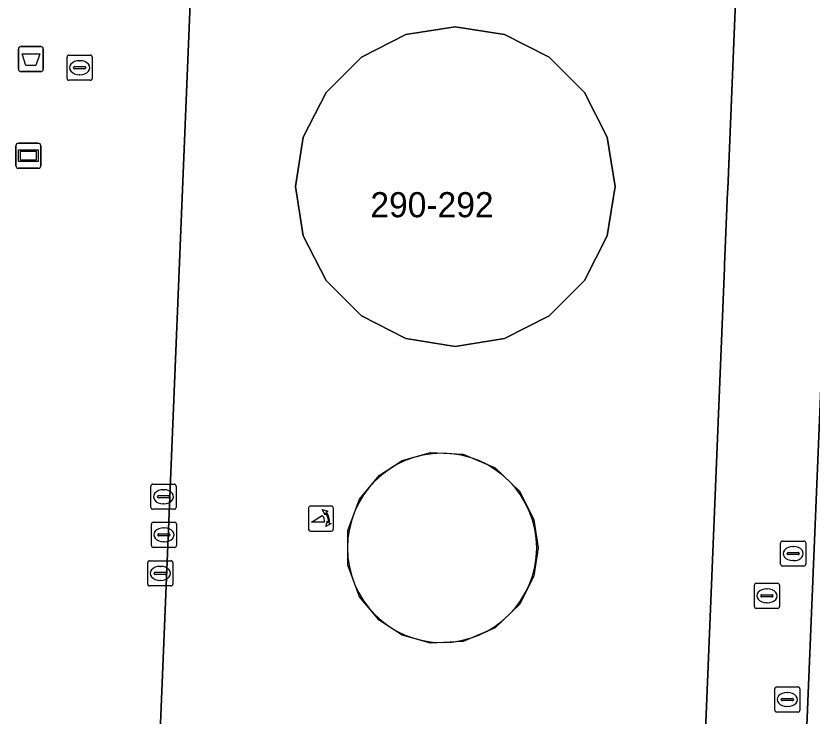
# Model space of a CAD drawing. Extents: x 160888 to 161385, y 386490 to 386908.
# Drawn here: x 161238.26 to 161269.97, y 386705.95 to 386733.83 of the extents above; entities that cross this region are included whole.
import ezdxf

# ---------------------------------------------------------------- set-up
doc = ezdxf.new("R2010")
doc.units = 0
for name, color, linetype in [('IMGEO_Afvalbak', 7, 'Continuous'), ('IMGEO_Kolk', 7, 'Continuous'), ('IMGEO_Pand', 7, 'Continuous'), ('IMGEO_Pand_nummerreeks', 7, 'Continuous'), ('IMGEO_Pand_overbouw', 7, 'Continuous'), ('IMGEO_Poller', 7, 'Continuous'), ('IMGEO_Reclamebord', 7, 'Continuous'), ('IMGEO_Rioolput', 7, 'Continuous'), ('IMGEO_Voetgangersgebied_open', 7, 'Continuous'), ('IMGEO_Voetpad_open', 7, 'Continuous')]:
    doc.layers.add(name, color=color, linetype=linetype)

msp = doc.modelspace()

# ---------------------------------------------------------------- linework, layer by layer
at = {"layer": 'IMGEO_Afvalbak'}
for p, q in [((161238.358, 386731.708), (161238.358, 386732.508)), ((161238.358, 386732.508), (161238.358, 386731.708)), ((161238.458, 386732.608), (161239.248, 386732.608)), ((161239.248, 386732.608), (161238.458, 386732.608)), ((161239.348, 386732.508), (161239.348, 386731.708)), ((161239.348, 386731.708), (161239.348, 386732.508)), ((161239.248, 386731.608), (161238.458, 386731.608)), ((161238.458, 386731.608), (161239.248, 386731.608))]:
    msp.add_line(p, q, dxfattribs=at)
msp.add_lwpolyline([(161238.501, 386732.322), (161239.205, 386732.322), (161239.056, 386731.852), (161238.65, 386731.852), (161238.501, 386732.322)], dxfattribs=at)
for centre, start, end in [((161238.458, 386732.508), 90, 180), ((161238.458, 386732.508), 90, 180), ((161239.248, 386732.508), 0, 90), ((161239.248, 386732.508), 360, 90), ((161238.458, 386731.708), 180, 270), ((161238.458, 386731.708), 180, 270), ((161239.248, 386731.708), 270, 0), ((161239.248, 386731.708), 270, 0)]:
    msp.add_arc(centre, 0.1, start, end, dxfattribs=at)
at = {"layer": 'IMGEO_Kolk'}
for p, q in [((161240.293, 386731.339), (161240.293, 386732.191)), ((161240.368, 386732.265), (161241.22, 386732.265)), ((161241.294, 386732.191), (161241.294, 386731.339)), ((161240.781, 386732.045), (161240.806, 386732.045)), ((161240.552, 386731.759), (161240.552, 386731.771)), ((161240.99, 386731.722), (161240.592, 386731.722)), ((161240.595, 386731.808), (161240.993, 386731.808)), ((161241.036, 386731.771), (161241.036, 386731.759)), ((161241.22, 386731.265), (161240.368, 386731.265)), ((161240.804, 386731.485), (161240.779, 386731.485))]:
    msp.add_line(p, q, dxfattribs=at)
for points in [[(161240.293, 386731.339), (161240.293, 386732.191)], [(161240.368, 386732.265), (161241.22, 386732.265)], [(161241.294, 386732.191), (161241.294, 386731.339)], [(161241.22, 386731.265), (161240.368, 386731.265)]]:
    msp.add_lwpolyline(points, dxfattribs=at)
for centre, radius, start, end in [((161240.37, 386732.189), 0.0765, 91.552, 178.448), ((161240.37, 386732.189), 0.0765, 91.552, 178.448), ((161241.218, 386732.189), 0.0765, 1.552, 88.448), ((161241.218, 386732.189), 0.0765, 1.552, 88.448), ((161240.592, 386731.768), 0.0403, 85.8775, 175.7526), ((161240.589, 386731.758), 0.0366, 178.938, 274.7102), ((161240.993, 386731.765), 0.043, 264.8664, 352.4533), ((161240.997, 386731.77), 0.0386, 1.7309, 96.639), ((161240.37, 386731.341), 0.0765, 181.552, 268.448), ((161240.37, 386731.341), 0.0765, 181.552, 268.448), ((161241.218, 386731.341), 0.0765, 271.552, 358.448), ((161241.218, 386731.341), 0.0765, 271.552, 358.448)]:
    msp.add_arc(centre, radius, start, end, dxfattribs=at)
for centre, major_axis, ratio, start_param, end_param in [((161240.78, 386731.765), (-0.387, 0.002), 0.722429, 4.712389, 7.853982), ((161240.805, 386731.765), (-0.39, 0.002), 0.717154, 1.570796, 4.712389)]:
    msp.add_ellipse(centre, major_axis=major_axis, ratio=ratio, start_param=start_param, end_param=end_param, dxfattribs=at)
at = {"layer": 'IMGEO_Pand'}
msp.add_lwpolyline([(161257.725, 386720.977), (161259.499, 386721.882), (161260.908, 386723.29), (161261.812, 386725.064), (161262.123, 386727.031), (161261.812, 386728.998), (161260.908, 386730.772), (161259.499, 386732.18), (161257.725, 386733.084), (161255.758, 386733.396), (161253.791, 386733.084), (161252.017, 386732.18), (161250.609, 386730.772), (161249.705, 386728.998), (161249.393, 386727.031), (161249.705, 386725.064), (161250.609, 386723.29), (161252.017, 386721.882), (161253.791, 386720.977), (161255.758, 386720.666)], close=True, dxfattribs=at)
at = {"layer": 'IMGEO_Pand_overbouw'}
for points in [[(161267.088, 386738.621), (161245.413, 386739.487), (161243.237, 386686.658), (161264.93, 386685.782)], [(161257.725, 386720.977), (161255.758, 386720.666), (161253.791, 386720.977), (161252.017, 386721.882), (161250.609, 386723.29), (161249.705, 386725.064), (161249.393, 386727.031), (161249.705, 386728.998), (161250.609, 386730.772), (161252.017, 386732.18), (161253.791, 386733.084), (161255.758, 386733.396), (161257.725, 386733.084), (161259.499, 386732.18), (161260.908, 386730.772), (161261.812, 386728.998), (161262.123, 386727.031), (161261.812, 386725.064), (161260.908, 386723.29), (161259.499, 386721.882)], [(161259.055, 386712.644), (161258.89, 386711.533), (161258.325, 386710.398), (161257.341, 386709.456), (161256.074, 386708.915), (161254.769, 386708.85), (161253.639, 386709.169), (161252.725, 386709.759), (161251.942, 386710.698), (161251.473, 386711.952), (161251.473, 386713.335), (161251.942, 386714.589), (161252.725, 386715.529), (161253.639, 386716.118), (161254.769, 386716.438), (161256.074, 386716.372), (161257.341, 386715.832), (161258.325, 386714.889), (161258.89, 386713.754)]]:
    msp.add_lwpolyline(points, close=True, dxfattribs=at)
at = {"layer": 'IMGEO_Poller'}
for p, q in [((161249.91, 386714.213), (161249.91, 386713.406)), ((161249.91, 386714.213), (161249.91, 386713.406)), ((161250.812, 386714.308), (161250.004, 386714.308)), ((161250.812, 386714.308), (161250.004, 386714.308)), ((161250.906, 386713.406), (161250.906, 386714.213)), ((161250.906, 386713.406), (161250.906, 386714.213)), ((161250.004, 386713.311), (161250.812, 386713.311)), ((161250.004, 386713.311), (161250.812, 386713.311))]:
    msp.add_line(p, q, dxfattribs=at)
for points in [[(161250.589, 386714.037), (161250.577, 386713.964), (161250.452, 386714.169)], [(161250.452, 386714.169), (161250.683, 386714.103), (161250.612, 386714.071)], [(161250.545, 386713.664), (161250.032, 386713.664), (161250.462, 386713.939)], [(161250.605, 386713.492), (161250.671, 386713.723), (161250.701, 386713.655)], [(161250.737, 386713.628), (161250.809, 386713.617), (161250.605, 386713.492)]]:
    msp.add_lwpolyline(points, dxfattribs=at)
for centre, radius, start, end in [((161250.004, 386714.213), 0.0946, 90, 180), ((161250.004, 386714.213), 0.0946, 90, 180), ((161250.812, 386714.213), 0.0946, 0, 90), ((161250.812, 386714.213), 0.0946, 0, 90), ((161250.217, 386713.714), 0.332, 351.3247, 42.4854), ((161250.231, 386713.724), 0.476, 351.7527, 41.1691), ((161250.231, 386713.724), 0.516, 349.3569, 42.2912), ((161250.004, 386713.406), 0.0946, 180, 270), ((161250.004, 386713.406), 0.0946, 180, 270), ((161250.812, 386713.406), 0.0946, 270, 0), ((161250.812, 386713.406), 0.0946, 270, 0)]:
    msp.add_arc(centre, radius, start, end, dxfattribs=at)
at = {"layer": 'IMGEO_Reclamebord'}
for p, q in [((161238.357, 386728.759), (161239.147, 386728.759)), ((161239.147, 386728.759), (161238.357, 386728.759)), ((161238.257, 386727.859), (161238.257, 386728.659)), ((161238.257, 386728.659), (161238.257, 386727.859)), ((161239.247, 386728.659), (161239.247, 386727.859)), ((161239.247, 386727.859), (161239.247, 386728.659)), ((161239.147, 386727.759), (161238.357, 386727.759)), ((161238.357, 386727.759), (161239.147, 386727.759))]:
    msp.add_line(p, q, dxfattribs=at)
for points in [[(161238.358, 386728.491), (161239.146, 386728.491), (161239.146, 386728.027), (161238.358, 386728.027), (161238.358, 386728.491)], [(161238.423, 386728.426), (161238.423, 386728.092), (161239.081, 386728.092), (161239.081, 386728.426), (161238.423, 386728.426)]]:
    msp.add_lwpolyline(points, dxfattribs=at)
for centre, start, end in [((161238.357, 386728.659), 90, 180), ((161238.357, 386728.659), 90, 180), ((161239.147, 386728.659), 0, 90), ((161239.147, 386728.659), 360, 90), ((161238.357, 386727.859), 180, 270), ((161238.357, 386727.859), 180, 270), ((161239.147, 386727.859), 270, 0), ((161239.147, 386727.859), 270, 0)]:
    msp.add_arc(centre, 0.1, start, end, dxfattribs=at)
at = {"layer": 'IMGEO_Rioolput'}
for p, q in [((161243.637, 386714.254), (161243.637, 386715.106)), ((161243.712, 386715.18), (161244.564, 386715.18)), ((161244.638, 386715.106), (161244.638, 386714.254)), ((161244.125, 386714.96), (161244.15, 386714.96)), ((161243.896, 386714.674), (161243.896, 386714.686)), ((161244.334, 386714.637), (161243.936, 386714.637)), ((161243.939, 386714.723), (161244.337, 386714.723)), ((161244.38, 386714.686), (161244.38, 386714.674)), ((161244.564, 386714.18), (161243.712, 386714.18)), ((161244.148, 386714.4), (161244.123, 386714.4)), ((161243.652, 386712.737), (161243.652, 386713.589)), ((161243.727, 386713.663), (161244.579, 386713.663)), ((161244.653, 386713.589), (161244.653, 386712.737)), ((161243.911, 386713.157), (161243.911, 386713.169)), ((161243.954, 386713.206), (161244.352, 386713.206)), ((161244.14, 386713.443), (161244.165, 386713.443)), ((161244.395, 386713.169), (161244.395, 386713.157)), ((161244.349, 386713.12), (161243.951, 386713.12)), ((161244.163, 386712.883), (161244.138, 386712.883)), ((161268.719, 386711.991), (161268.719, 386712.843)), ((161268.794, 386712.917), (161269.646, 386712.917)), ((161269.72, 386712.843), (161269.72, 386711.991)), ((161244.579, 386712.663), (161243.727, 386712.663)), ((161269.207, 386712.697), (161269.232, 386712.697)), ((161268.978, 386712.411), (161268.978, 386712.423)), ((161269.416, 386712.374), (161269.018, 386712.374)), ((161269.021, 386712.46), (161269.419, 386712.46)), ((161269.462, 386712.423), (161269.462, 386712.411)), ((161243.506, 386711.202), (161243.506, 386712.054)), ((161243.581, 386712.128), (161244.433, 386712.128)), ((161243.994, 386711.908), (161244.019, 386711.908)), ((161244.507, 386712.054), (161244.507, 386711.202)), ((161269.646, 386711.917), (161268.794, 386711.917)), ((161269.23, 386712.137), (161269.205, 386712.137)), ((161243.765, 386711.622), (161243.765, 386711.634)), ((161244.203, 386711.585), (161243.805, 386711.585)), ((161243.808, 386711.671), (161244.206, 386711.671)), ((161244.249, 386711.634), (161244.249, 386711.622)), ((161244.017, 386711.348), (161243.992, 386711.348)), ((161244.433, 386711.128), (161243.581, 386711.128)), ((161267.673, 386710.308), (161267.673, 386711.16)), ((161267.748, 386711.234), (161268.6, 386711.234)), ((161268.161, 386711.014), (161268.186, 386711.014)), ((161268.674, 386711.16), (161268.674, 386710.308)), ((161267.932, 386710.728), (161267.932, 386710.74)), ((161268.37, 386710.691), (161267.972, 386710.691)), ((161267.975, 386710.777), (161268.373, 386710.777)), ((161268.416, 386710.74), (161268.416, 386710.728)), ((161268.184, 386710.454), (161268.159, 386710.454)), ((161268.6, 386710.234), (161267.748, 386710.234)), ((161268.485, 386706.178), (161268.485, 386707.03)), ((161268.56, 386707.104), (161269.412, 386707.104)), ((161268.973, 386706.884), (161268.998, 386706.884)), ((161269.486, 386707.03), (161269.486, 386706.178)), ((161268.744, 386706.598), (161268.744, 386706.61)), ((161269.182, 386706.561), (161268.784, 386706.561)), ((161268.787, 386706.647), (161269.185, 386706.647)), ((161269.228, 386706.61), (161269.228, 386706.598)), ((161268.996, 386706.324), (161268.971, 386706.324)), ((161269.412, 386706.104), (161268.56, 386706.104))]:
    msp.add_line(p, q, dxfattribs=at)
for points in [[(161243.637, 386714.254), (161243.637, 386715.106)], [(161243.712, 386715.18), (161244.564, 386715.18)], [(161244.638, 386715.106), (161244.638, 386714.254)], [(161244.564, 386714.18), (161243.712, 386714.18)], [(161243.652, 386712.737), (161243.652, 386713.589)], [(161243.727, 386713.663), (161244.579, 386713.663)], [(161244.653, 386713.589), (161244.653, 386712.737)], [(161268.719, 386711.991), (161268.719, 386712.843)], [(161268.794, 386712.917), (161269.646, 386712.917)], [(161269.72, 386712.843), (161269.72, 386711.991)], [(161244.579, 386712.663), (161243.727, 386712.663)], [(161243.506, 386711.202), (161243.506, 386712.054)], [(161243.581, 386712.128), (161244.433, 386712.128)], [(161244.507, 386712.054), (161244.507, 386711.202)], [(161269.646, 386711.917), (161268.794, 386711.917)], [(161244.433, 386711.128), (161243.581, 386711.128)], [(161267.673, 386710.308), (161267.673, 386711.16)], [(161267.748, 386711.234), (161268.6, 386711.234)], [(161268.674, 386711.16), (161268.674, 386710.308)], [(161268.6, 386710.234), (161267.748, 386710.234)], [(161268.485, 386706.178), (161268.485, 386707.03)], [(161268.56, 386707.104), (161269.412, 386707.104)], [(161269.486, 386707.03), (161269.486, 386706.178)], [(161269.412, 386706.104), (161268.56, 386706.104)]]:
    msp.add_lwpolyline(points, dxfattribs=at)
for centre, radius, start, end in [((161243.714, 386715.104), 0.0765, 91.552, 178.448), ((161243.714, 386715.104), 0.0765, 91.552, 178.448), ((161244.562, 386715.104), 0.0765, 1.552, 88.448), ((161244.562, 386715.104), 0.0765, 1.552, 88.448), ((161243.936, 386714.683), 0.0403, 85.8775, 175.7526), ((161243.933, 386714.673), 0.0366, 178.938, 274.7102), ((161244.337, 386714.68), 0.043, 264.8664, 352.4533), ((161244.341, 386714.685), 0.0386, 1.7309, 96.639), ((161243.714, 386714.256), 0.0765, 181.552, 268.448), ((161243.714, 386714.256), 0.0765, 181.552, 268.448), ((161244.562, 386714.256), 0.0765, 271.552, 358.448), ((161244.562, 386714.256), 0.0765, 271.552, 358.448), ((161243.729, 386713.587), 0.0765, 91.552, 178.448), ((161243.729, 386713.587), 0.0765, 91.552, 178.448), ((161244.577, 386713.587), 0.0765, 1.552, 88.448), ((161244.577, 386713.587), 0.0765, 1.552, 88.448), ((161243.951, 386713.166), 0.0403, 85.8775, 175.7526), ((161243.948, 386713.156), 0.0366, 178.938, 274.7102), ((161244.352, 386713.163), 0.043, 264.8664, 352.4533), ((161244.356, 386713.168), 0.0386, 1.7309, 96.639), ((161268.796, 386712.841), 0.0765, 91.552, 178.448), ((161268.796, 386712.841), 0.0765, 91.552, 178.448), ((161269.644, 386712.841), 0.0765, 1.552, 88.448), ((161269.644, 386712.841), 0.0765, 1.552, 88.448), ((161243.729, 386712.739), 0.0765, 181.552, 268.448), ((161243.729, 386712.739), 0.0765, 181.552, 268.448), ((161244.577, 386712.739), 0.0765, 271.552, 358.448), ((161244.577, 386712.739), 0.0765, 271.552, 358.448), ((161269.018, 386712.42), 0.0403, 85.8775, 175.7526), ((161269.015, 386712.41), 0.0366, 178.938, 274.7102), ((161269.419, 386712.417), 0.043, 264.8664, 352.4533), ((161269.423, 386712.422), 0.0386, 1.7309, 96.639), ((161243.583, 386712.052), 0.0765, 91.552, 178.448), ((161243.583, 386712.052), 0.0765, 91.552, 178.448), ((161244.431, 386712.052), 0.0765, 1.552, 88.448), ((161244.431, 386712.052), 0.0765, 1.552, 88.448), ((161268.796, 386711.993), 0.0765, 181.552, 268.448), ((161268.796, 386711.993), 0.0765, 181.552, 268.448), ((161269.644, 386711.993), 0.0765, 271.552, 358.448), ((161269.644, 386711.993), 0.0765, 271.552, 358.448), ((161243.805, 386711.631), 0.0403, 85.8775, 175.7526), ((161243.802, 386711.621), 0.0366, 178.938, 274.7102), ((161244.206, 386711.628), 0.043, 264.8664, 352.4533), ((161244.21, 386711.633), 0.0386, 1.7309, 96.639), ((161243.583, 386711.204), 0.0765, 181.552, 268.448), ((161243.583, 386711.204), 0.0765, 181.552, 268.448), ((161244.431, 386711.204), 0.0765, 271.552, 358.448), ((161244.431, 386711.204), 0.0765, 271.552, 358.448), ((161267.75, 386711.158), 0.0765, 91.552, 178.448), ((161267.75, 386711.158), 0.0765, 91.552, 178.448), ((161268.598, 386711.158), 0.0765, 1.552, 88.448), ((161268.598, 386711.158), 0.0765, 1.552, 88.448), ((161267.972, 386710.737), 0.0403, 85.8775, 175.7526), ((161267.969, 386710.727), 0.0366, 178.938, 274.7102), ((161268.373, 386710.734), 0.043, 264.8664, 352.4533), ((161268.377, 386710.739), 0.0386, 1.7309, 96.639), ((161267.75, 386710.31), 0.0765, 181.552, 268.448), ((161267.75, 386710.31), 0.0765, 181.552, 268.448), ((161268.598, 386710.31), 0.0765, 271.552, 358.448), ((161268.598, 386710.31), 0.0765, 271.552, 358.448), ((161268.562, 386707.028), 0.0765, 91.552, 178.448), ((161268.562, 386707.028), 0.0765, 91.552, 178.448), ((161269.41, 386707.028), 0.0765, 1.552, 88.448), ((161269.41, 386707.028), 0.0765, 1.552, 88.448), ((161268.784, 386706.607), 0.0403, 85.8775, 175.7526), ((161268.781, 386706.597), 0.0366, 178.938, 274.7102), ((161269.185, 386706.604), 0.043, 264.8664, 352.4533), ((161269.189, 386706.609), 0.0386, 1.7309, 96.639), ((161268.562, 386706.18), 0.0765, 181.552, 268.448), ((161268.562, 386706.18), 0.0765, 181.552, 268.448), ((161269.41, 386706.18), 0.0765, 271.552, 358.448), ((161269.41, 386706.18), 0.0765, 271.552, 358.448)]:
    msp.add_arc(centre, radius, start, end, dxfattribs=at)
for centre, major_axis, ratio, start_param, end_param in [((161244.124, 386714.68), (-0.387, 0.002), 0.722429, 4.712389, 7.853982), ((161244.149, 386714.68), (-0.39, 0.002), 0.717154, 1.570796, 4.712389), ((161244.139, 386713.163), (-0.387, 0.002), 0.722429, 4.712389, 7.853982), ((161244.164, 386713.163), (-0.39, 0.002), 0.717154, 1.570796, 4.712389), ((161269.206, 386712.417), (-0.387, 0.002), 0.722429, 4.712389, 7.853982), ((161269.231, 386712.417), (-0.39, 0.002), 0.717154, 1.570796, 4.712389), ((161243.993, 386711.628), (-0.387, 0.002), 0.722429, 4.712389, 7.853982), ((161244.018, 386711.628), (-0.39, 0.002), 0.717154, 1.570796, 4.712389), ((161268.16, 386710.734), (-0.387, 0.002), 0.722429, 4.712389, 7.853982), ((161268.185, 386710.734), (-0.39, 0.002), 0.717154, 1.570796, 4.712389), ((161268.972, 386706.604), (-0.387, 0.002), 0.722429, 4.712389, 7.853982), ((161268.997, 386706.604), (-0.39, 0.002), 0.717154, 1.570796, 4.712389)]:
    msp.add_ellipse(centre, major_axis=major_axis, ratio=ratio, start_param=start_param, end_param=end_param, dxfattribs=at)
at = {"layer": 'IMGEO_Voetgangersgebied_open'}
msp.add_lwpolyline([(161268.446, 386680.472), (161268.551, 386683.179), (161268.831, 386683.148), (161271.405, 386745.286)], dxfattribs=at)
msp.add_lwpolyline([(161245.413, 386739.487), (161267.088, 386738.621), (161266.611, 386726.928), (161266.606, 386726.811), (161266.487, 386723.909), (161266.483, 386723.792), (161265.214, 386692.746), (161265.091, 386689.722), (161264.93, 386685.782), (161243.237, 386686.658)], close=True, dxfattribs=at)
at = {"layer": 'IMGEO_Voetpad_open'}
msp.add_lwpolyline([(161271.321, 386730.8), (161271.734, 386745.267), (161271.405, 386745.286), (161268.831, 386683.148), (161269.282, 386683.091)], dxfattribs=at)
for points in [[(161266.606, 386726.811), (161266.611, 386726.928), (161267.088, 386738.621), (161245.413, 386739.487), (161243.237, 386686.658), (161264.93, 386685.782), (161265.091, 386689.722), (161265.214, 386692.746), (161266.483, 386723.792), (161266.487, 386723.909)], [(161255.758, 386720.666), (161253.791, 386720.977), (161252.017, 386721.882), (161250.609, 386723.29), (161249.705, 386725.064), (161249.393, 386727.031), (161249.705, 386728.998), (161250.609, 386730.772), (161252.017, 386732.18), (161253.791, 386733.084), (161255.758, 386733.396), (161257.725, 386733.084), (161259.499, 386732.18), (161260.908, 386730.772), (161261.812, 386728.998), (161262.123, 386727.031), (161261.812, 386725.064), (161260.908, 386723.29), (161259.499, 386721.882), (161257.725, 386720.977)]]:
    msp.add_lwpolyline(points, close=True, dxfattribs=at)
for start, end in [(90, 270), (90, 270), (270, 90), (270, 90)]:
    msp.add_arc((161255.232, 386712.644), 3.77, start, end, dxfattribs=at)

# ---------------------------------------------------------------- texts
at = {"layer": 'IMGEO_Pand_nummerreeks'}
msp.add_text('290-292', height=1, dxfattribs=at).set_placement((161252.377, 386725.81))

doc.saveas('drawing.dxf')
